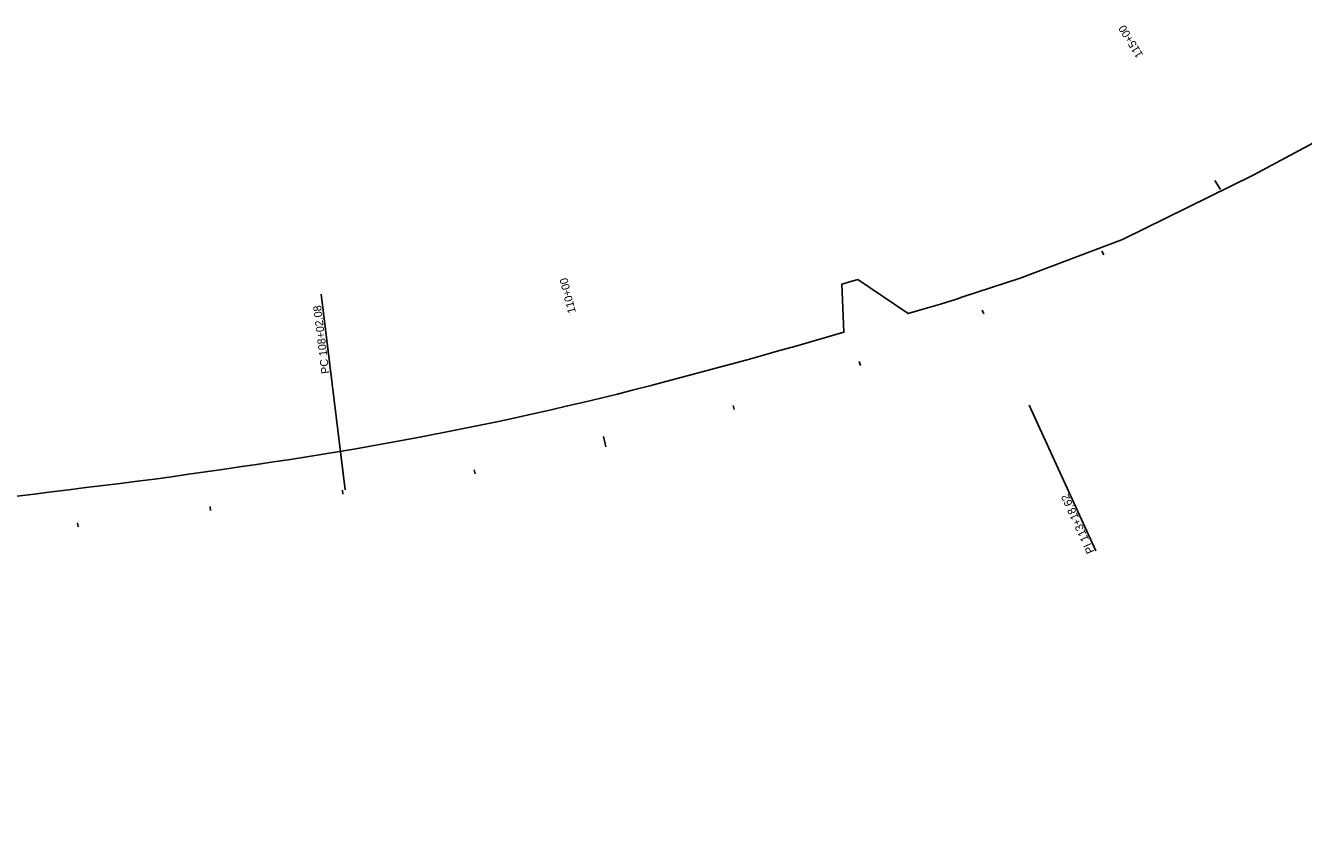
# Model space of a CAD drawing. Extents: x 1568908 to 1572777, y 730965 to 733090.
# Drawn here: x 1570843 to 1571801, y 732028 to 732629 of the extents above; entities that cross this region are included whole.
import ezdxf

# ---------------------------------------------------------------- set-up
doc = ezdxf.new("R2010")
doc.units = 0
doc.layers.add('R_Horz Alg Annot', color=7, linetype='Continuous')
doc.layers.add('R_No Plot', color=7, linetype='Continuous')

msp = doc.modelspace()

# ---------------------------------------------------------------- linework, layer by layer
at = {"layer": 'R_Horz Alg Annot'}
for points in [[(1571734.19, 732512.66), (1571738.37, 732505.84)], [(1571650.86, 732457.02), (1571649.45, 732459.67)], [(1571082.41, 732280.73), (1571064.28, 732427.34)], [(1571561, 732412.75), (1571559.76, 732415.48)], [(1571468.61, 732374.05), (1571467.54, 732376.85)], [(1571374.03, 732341.07), (1571373.13, 732343.93)], [(1571595.05, 732344.13), (1571644.93, 732234.99)], [(1571275.93, 732320.71), (1571277.86, 732312.94)], [(1571179.72, 732292.7), (1571179.18, 732295.65)], [(1571080.72, 732277.5), (1571080.35, 732280.48)], [(1570981.47, 732265.23), (1570981.1, 732268.21)], [(1570882.23, 732252.95), (1570881.86, 732255.93)]]:
    msp.add_lwpolyline(points, dxfattribs=at)
at = {"layer": 'R_No Plot'}
for points in [[(1572777.39, 731519.96), (1571905.83, 732616.57), (1571828.51, 732551.75), (1571762.8, 732516.69), (1571664.98, 732468.4), (1571588.26, 732439.45), (1571544.6, 732425.09)], [(1572777.39, 731519.96), (1571905.83, 732616.57), (1571828.51, 732551.75), (1571762.8, 732516.69), (1571664.98, 732468.4), (1571588.26, 732439.45), (1571544.6, 732425.09)], [(1572777.39, 731519.96), (1571905.83, 732616.57), (1571828.51, 732551.75), (1571762.8, 732516.69), (1571664.98, 732468.4), (1571588.26, 732439.45), (1571544.6, 732425.09)], [(1572777.39, 731519.96), (1571905.83, 732616.57), (1571828.51, 732551.75), (1571762.8, 732516.69), (1571664.98, 732468.4), (1571588.26, 732439.45), (1571544.6, 732425.09)], [(1571544.6, 732425.09), (1571540.52, 732423.79), (1571528.51, 732419.94), (1571516.43, 732416.4), (1571504.36, 732412.85), (1571466.64, 732438.45), (1571454.57, 732434.9), (1571456.21, 732398.85), (1571432.22, 732391.94), (1571420.08, 732388.52), (1571407.95, 732385.1), (1571395.82, 732381.68), (1571383.68, 732378.26), (1571371.49, 732375.01), (1571359.3, 732371.75), (1571347.11, 732368.49), (1571334.93, 732365.24), (1571322.8, 732362.04), (1571310.67, 732358.84), (1571298.54, 732355.64), (1571286.41, 732352.44), (1571273.98, 732349.5), (1571261.55, 732346.56), (1571249.12, 732343.61), (1571236.69, 732340.67), (1571224.35, 732337.97), (1571212.01, 732335.27), (1571199.67, 732332.57), (1571187.33, 732329.87), (1571163.51, 732325.17), (1571139.68, 732320.46), (1571127.35, 732318.19), (1571115.01, 732315.92), (1571102.68, 732313.66), (1571090.34, 732311.39), (1571065.9, 732307.45), (1571041.46, 732303.51), (1571028.73, 732301.65), (1571016, 732299.78), (1571003.27, 732297.92), (1570990.54, 732296.06), (1570977.81, 732294.23), (1570965.07, 732292.41), (1570952.33, 732290.59), (1570939.59, 732288.77), (1570926.73, 732287.18), (1570913.87, 732285.58), (1570901, 732283.99), (1570888.14, 732282.4), (1570875.22, 732280.79), (1570862.3, 732279.19), (1570849.37, 732277.58), (1570836.45, 732275.97)], [(1571544.6, 732425.09), (1571540.52, 732423.79), (1571528.51, 732419.94), (1571516.43, 732416.4), (1571504.36, 732412.85), (1571466.64, 732438.45), (1571454.57, 732434.9), (1571456.21, 732398.85), (1571432.22, 732391.94), (1571420.08, 732388.52), (1571407.95, 732385.1), (1571395.82, 732381.68), (1571383.68, 732378.26), (1571371.49, 732375.01), (1571359.3, 732371.75), (1571347.11, 732368.49), (1571334.93, 732365.24), (1571322.8, 732362.04), (1571310.67, 732358.84), (1571298.54, 732355.64), (1571286.41, 732352.44), (1571273.98, 732349.5), (1571261.55, 732346.56), (1571249.12, 732343.61), (1571236.69, 732340.67), (1571224.35, 732337.97), (1571212.01, 732335.27), (1571199.67, 732332.57), (1571187.33, 732329.87), (1571163.51, 732325.17), (1571139.68, 732320.46), (1571127.35, 732318.19), (1571115.01, 732315.92), (1571102.68, 732313.66), (1571090.34, 732311.39), (1571065.9, 732307.45), (1571041.46, 732303.51), (1571028.73, 732301.65), (1571016, 732299.78), (1571003.27, 732297.92), (1570990.54, 732296.06), (1570977.81, 732294.23), (1570965.07, 732292.41), (1570952.33, 732290.59), (1570939.59, 732288.77), (1570926.73, 732287.18), (1570913.87, 732285.58), (1570901, 732283.99), (1570888.14, 732282.4), (1570875.22, 732280.79), (1570862.3, 732279.19), (1570849.37, 732277.58), (1570836.45, 732275.97)], [(1571544.6, 732425.09), (1571540.52, 732423.79), (1571528.51, 732419.94), (1571516.43, 732416.4), (1571504.36, 732412.85), (1571466.64, 732438.45), (1571454.57, 732434.9), (1571456.21, 732398.85), (1571432.22, 732391.94), (1571420.08, 732388.52), (1571407.95, 732385.1), (1571395.82, 732381.68), (1571383.68, 732378.26), (1571371.49, 732375.01), (1571359.3, 732371.75), (1571347.11, 732368.49), (1571334.93, 732365.24), (1571322.8, 732362.04), (1571310.67, 732358.84), (1571298.54, 732355.64), (1571286.41, 732352.44), (1571273.98, 732349.5), (1571261.55, 732346.56), (1571249.12, 732343.61), (1571236.69, 732340.67), (1571224.35, 732337.97), (1571212.01, 732335.27), (1571199.67, 732332.57), (1571187.33, 732329.87), (1571163.51, 732325.17), (1571139.68, 732320.46), (1571127.35, 732318.19), (1571115.01, 732315.92), (1571102.68, 732313.66), (1571090.34, 732311.39), (1571065.9, 732307.45), (1571041.46, 732303.51), (1571028.73, 732301.65), (1571016, 732299.78), (1571003.27, 732297.92), (1570990.54, 732296.06), (1570977.81, 732294.23), (1570965.07, 732292.41), (1570952.33, 732290.59), (1570939.59, 732288.77), (1570926.73, 732287.18), (1570913.87, 732285.58), (1570901, 732283.99), (1570888.14, 732282.4), (1570875.22, 732280.79), (1570862.3, 732279.19), (1570849.37, 732277.58), (1570836.45, 732275.97)], [(1571544.6, 732425.09), (1571540.52, 732423.79), (1571528.51, 732419.94), (1571516.43, 732416.4), (1571504.36, 732412.85), (1571466.64, 732438.45), (1571454.57, 732434.9), (1571456.21, 732398.85), (1571432.22, 732391.94), (1571420.08, 732388.52), (1571407.95, 732385.1), (1571395.82, 732381.68), (1571383.68, 732378.26), (1571371.49, 732375.01), (1571359.3, 732371.75), (1571347.11, 732368.49), (1571334.93, 732365.24), (1571322.8, 732362.04), (1571310.67, 732358.84), (1571298.54, 732355.64), (1571286.41, 732352.44), (1571273.98, 732349.5), (1571261.55, 732346.56), (1571249.12, 732343.61), (1571236.69, 732340.67), (1571224.35, 732337.97), (1571212.01, 732335.27), (1571199.67, 732332.57), (1571187.33, 732329.87), (1571163.51, 732325.17), (1571139.68, 732320.46), (1571127.35, 732318.19), (1571115.01, 732315.92), (1571102.68, 732313.66), (1571090.34, 732311.39), (1571065.9, 732307.45), (1571041.46, 732303.51), (1571028.73, 732301.65), (1571016, 732299.78), (1571003.27, 732297.92), (1570990.54, 732296.06), (1570977.81, 732294.23), (1570965.07, 732292.41), (1570952.33, 732290.59), (1570939.59, 732288.77), (1570926.73, 732287.18), (1570913.87, 732285.58), (1570901, 732283.99), (1570888.14, 732282.4), (1570875.22, 732280.79), (1570862.3, 732279.19), (1570849.37, 732277.58), (1570836.45, 732275.97)]]:
    msp.add_lwpolyline(points, dxfattribs=at)

# ---------------------------------------------------------------- texts
at = {"layer": 'R_Horz Alg Annot'}
for s, rotation, p in [('115+00', 121.47725, (1571680.73, 732606.8)), ('110+00', 103.97725, (1571255.33, 732413.92)), ('PC 108+02.08', 97.05, (1571070.59, 732368.14)), ('PI 113+18.62', 114.56247, (1571644.02, 732234.58))]:
    msp.add_text(s, height=6, rotation=rotation, dxfattribs=at).set_placement(p)

doc.saveas('drawing.dxf')
